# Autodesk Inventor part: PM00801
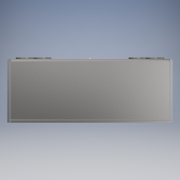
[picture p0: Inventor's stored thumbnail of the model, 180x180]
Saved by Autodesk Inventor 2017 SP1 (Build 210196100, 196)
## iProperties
Created: 2021-08
Part Number: PM00801
Material: Generico
Document SubType Name: Modeling
Designer: ROSSETTO
Density: 1 g/cm^3
Appearance: Default
Author: ROSSETTO
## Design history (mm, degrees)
derived "BC26915 (Complessivo piastra fissaggio colonna doccia-vasca "
node "Solido1"
node "Lastra piegata per incasso colonna vasca doccia da terra P36"
sketch "Schizzo1"
  geometry: 1 further point
  dimensions: "d0" = 10 dimension on point (0, 0)
node "Inserto a strappo filettato M8.ipt:1"
node "Inserto a strappo filettato M8.ipt:2"
node "Inserto a strappo filettato M8.ipt:3"
node "Inserto a strappo filettato M8.ipt:4"
node "Inserto a strappo filettato M8.ipt:5"
node "Inserto a strappo filettato M8.ipt:6"
node "Inserto a strappo filettato M8.ipt:7"
node "Inserto a strappo filettato M8.ipt:8"
